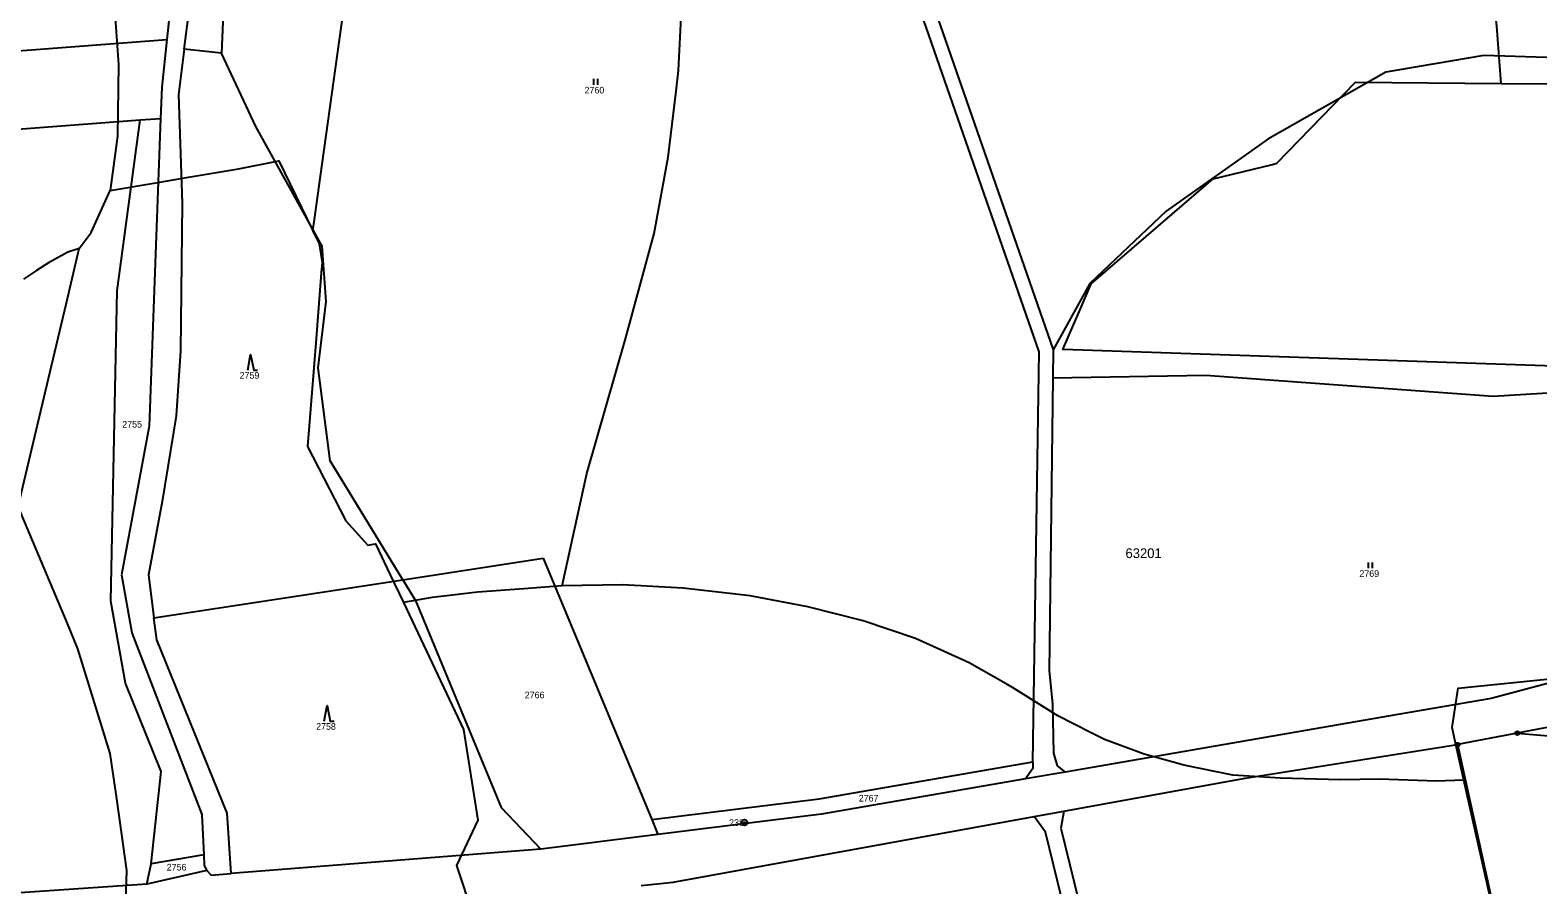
# Model space of a CAD drawing. Extents: x -546762 to -540209, y -1046851 to -1035694.
# Drawn here: x -540838.1 to -540451.5, y -1039687.3 to -1039468.3 of the extents above; entities that cross this region are included whole.
import ezdxf

# ---------------------------------------------------------------- set-up
doc = ezdxf.new("R2010")
doc.units = 0
for name, color, linetype in [('Vrstva 1', 7, 'Continuous'), ('Vrstva 17', 7, 'Continuous'), ('Vrstva 18', 7, 'Continuous'), ('Vrstva 24', 7, 'Continuous'), ('Vrstva 25', 7, 'Continuous'), ('Vrstva 52', 7, 'Continuous'), ('Vrstva 53', 7, 'Continuous')]:
    doc.layers.add(name, color=color, linetype=linetype)

msp = doc.modelspace()

# ---------------------------------------------------------------- linework, layer by layer
at = {"layer": 'Vrstva 1'}
msp.add_line((-540456.76, -1039648.44), (-540432.8, -1039650.55), dxfattribs=at)
for points in [[(-540579.38, -1039550.73), (-540626.46, -1039415.41)], [(-540622.88, -1039414.93), (-540575.81, -1039550.19)], [(-540799.07, -1039433.72), (-540803.05, -1039470.73)], [(-540798.57, -1039473.16), (-540795.73, -1039450.85)], [(-540787.96, -1039450.05), (-540789, -1039474.2)], [(-540966.72, -1039483.15), (-540803.05, -1039470.73)], [(-540803.05, -1039470.73), (-540804.36, -1039482.91)], [(-540798.57, -1039473.16), (-540800.05, -1039484.79)], [(-540789, -1039474.2), (-540798.57, -1039473.16)], [(-540780.25, -1039493.01), (-540789, -1039474.2)], [(-540465.38, -1039474.8), (-540490.49, -1039479.1)], [(-540414.42, -1039476.4), (-540465.38, -1039474.8)], [(-540490.49, -1039479.1), (-540520.75, -1039496.26)], [(-540804.36, -1039482.91), (-540804.66, -1039490.91)], [(-540800.05, -1039484.79), (-540799.11, -1039512.61)], [(-540963.66, -1039502.97), (-540809.89, -1039491.31)], [(-540815.81, -1039535.11), (-540809.89, -1039491.31)], [(-540809.89, -1039491.31), (-540804.66, -1039490.91)], [(-540804.66, -1039490.91), (-540807.61, -1039569.76)], [(-540763.22, -1039523.67), (-540780.25, -1039493.01)], [(-540520.75, -1039496.26), (-540546.78, -1039514.67)], [(-540799.11, -1039512.61), (-540799.5, -1039550.5)], [(-540546.78, -1039514.67), (-540566.37, -1039533.18)], [(-540762.16, -1039537.82), (-540763.22, -1039523.67)], [(-540566.37, -1039533.18), (-540575.81, -1039550.19)], [(-540817.37, -1039614.58), (-540815.81, -1039535.11)], [(-540764.23, -1039554.84), (-540762.16, -1039537.82)], [(-540799.5, -1039550.5), (-540800.68, -1039567.12)], [(-540580.98, -1039655.8), (-540579.38, -1039550.73)], [(-540575.81, -1039550.19), (-540575.89, -1039557.42)], [(-540761.13, -1039578.68), (-540764.23, -1039554.84)], [(-540575.89, -1039557.42), (-540576.8, -1039632.44)], [(-540575.89, -1039557.42), (-540536.65, -1039556.7)], [(-540536.65, -1039556.7), (-540462.98, -1039562.13)], [(-540462.98, -1039562.13), (-540442.01, -1039560.77)], [(-540800.68, -1039567.12), (-540804.21, -1039589.05)], [(-540807.61, -1039569.76), (-540814.7, -1039607.89)], [(-540742.54, -1039609.11), (-540761.13, -1039578.68)], [(-540804.21, -1039589.05), (-540807.77, -1039607.88)], [(-540742.54, -1039609.11), (-540706.51, -1039603.62)], [(-540706.51, -1039603.62), (-540678.7, -1039670.58)], [(-540814.7, -1039607.89), (-540811.98, -1039622.71)], [(-540807.77, -1039607.88), (-540806.37, -1039618.86)], [(-540806.37, -1039618.86), (-540742.54, -1039609.11)], [(-540742.54, -1039609.11), (-540739.29, -1039614.44)], [(-540813.6, -1039635.67), (-540817.37, -1039614.58)], [(-540739.29, -1039614.44), (-540717.27, -1039667.45)], [(-540805.64, -1039624.55), (-540806.37, -1039618.86)], [(-540811.98, -1039622.71), (-540794.04, -1039669.3)], [(-540787.57, -1039668.92), (-540805.64, -1039624.55)], [(-540576.8, -1039632.44), (-540575.9, -1039640.89)], [(-540439.7, -1039633.2), (-540463.46, -1039639.54)], [(-540804.48, -1039658.3), (-540813.6, -1039635.67)], [(-540575.9, -1039640.89), (-540575.69, -1039653.53)], [(-540463.46, -1039639.54), (-540487.42, -1039643.67)], [(-540487.42, -1039643.67), (-540572.72, -1039658.42)], [(-540431.58, -1039643.66), (-540456.76, -1039648.44)], [(-540456.76, -1039648.44), (-540472.09, -1039651.38)], [(-540575.69, -1039653.53), (-540574.75, -1039656.79)], [(-540526.56, -1039660.01), (-540472.09, -1039651.38)], [(-540472.09, -1039651.38), (-540452.38, -1039740.97)], [(-540807.09, -1039681.9), (-540804.48, -1039658.3)], [(-540635.78, -1039665.26), (-540580.98, -1039655.8)], [(-540581.01, -1039657.47), (-540582.83, -1039660.17)], [(-540580.98, -1039655.8), (-540581.01, -1039657.47)], [(-540574.75, -1039656.79), (-540572.72, -1039658.42)], [(-540582.83, -1039660.17), (-540635.19, -1039669.22)], [(-540572.72, -1039658.42), (-540582.83, -1039660.17)], [(-540573.01, -1039668.44), (-540526.56, -1039660.01)], [(-540678.7, -1039670.58), (-540635.78, -1039665.26)], [(-540794.04, -1039669.3), (-540793.57, -1039679.58)], [(-540786.53, -1039684.37), (-540787.57, -1039668.92)], [(-540717.27, -1039667.45), (-540707.18, -1039678.13)], [(-540673.19, -1039686.62), (-540580.65, -1039669.82)], [(-540635.19, -1039669.22), (-540648.31, -1039670.85)], [(-540580.65, -1039669.82), (-540573.01, -1039668.44)], [(-540577.71, -1039673.82), (-540580.65, -1039669.82)], [(-540573.01, -1039668.44), (-540573.82, -1039672.77)], [(-540678.7, -1039670.58), (-540677.11, -1039674.41)], [(-540648.31, -1039670.85), (-540677.11, -1039674.41)], [(-540573.82, -1039672.77), (-540553.17, -1039756.65)], [(-540677.11, -1039674.41), (-540707.18, -1039678.13)], [(-540557.3, -1039757.2), (-540577.71, -1039673.82)], [(-540793.57, -1039679.58), (-540807.09, -1039681.9)], [(-540793.57, -1039679.58), (-540793.44, -1039682.35)], [(-540707.18, -1039678.13), (-540786.53, -1039684.37)], [(-540808.19, -1039687.11), (-540807.09, -1039681.9)], [(-540792.74, -1039683.59), (-540808.19, -1039687.11)], [(-540793.44, -1039682.35), (-540792.74, -1039683.59)], [(-540792.74, -1039683.59), (-540791.65, -1039684.82)], [(-540791.65, -1039684.82), (-540786.53, -1039684.37)], [(-540808.19, -1039687.11), (-541007.11, -1039700.75)], [(-540681.43, -1039687.49), (-540673.19, -1039686.62)]]:
    msp.add_lwpolyline(points, dxfattribs=at)
at = {"layer": 'Vrstva 24'}
for centre, radius in [((-540456.76, -1039648.44), 0.5), ((-540456.76, -1039648.44), 0.1), ((-540472.09, -1039651.38), 0.5), ((-540472.09, -1039651.38), 0.1), ((-540654.94, -1039671.35), 0.75), ((-540654.94, -1039671.35), 0.1)]:
    msp.add_circle(centre, radius, dxfattribs=at)
at = {"layer": 'Vrstva 25'}
for p, q in [((-540693.52, -1039482.32), (-540693.52, -1039480.82)), ((-540692.52, -1039482.32), (-540692.52, -1039480.82)), ((-540494.9, -1039606.2), (-540494.9, -1039604.7)), ((-540493.9, -1039606.2), (-540493.9, -1039604.7))]:
    msp.add_line(p, q, dxfattribs=at)
for points in [[(-540782.26, -1039555.4), (-540781.56, -1039551.4), (-540780.76, -1039555.4), (-540779.76, -1039555.4)], [(-540762.66, -1039645.36), (-540761.96, -1039641.36), (-540761.16, -1039645.36), (-540760.16, -1039645.36)]]:
    msp.add_lwpolyline(points, dxfattribs=at)
at = {"layer": 'Vrstva 52'}
for points in [[(-540765.6, -1039519.76), (-540765.19, -1039516.82), (-540762.78, -1039499.56), (-540762.18, -1039495.29), (-540757.82, -1039464.07), (-540755.99, -1039423.53), (-540754.94, -1039399.2), (-540754.94, -1039393.07), (-540754.94, -1039380.64), (-540757.03, -1039361.02), (-540758.37, -1039350.85), (-540758.97, -1039338.44), (-540758.22, -1039328.88), (-540756.88, -1039322), (-540756.26, -1039320.06), (-540754.49, -1039314.53), (-540747.09, -1039301.83), (-540735.59, -1039287.18), (-540734.98, -1039286.5), (-540730.2, -1039281.21), (-540728.36, -1039279.17), (-540725.92, -1039276.46), (-540718.34, -1039267.04)], [(-540833.47, -1039354.59), (-540833.93, -1039358.54), (-540833.73, -1039363.08), (-540833.52, -1039367.7), (-540833.41, -1039370.05), (-540833.15, -1039378.68), (-540830.79, -1039393.33), (-540829.59, -1039400.7), (-540828.88, -1039405.02), (-540828.77, -1039405.72), (-540827.58, -1039411.35), (-540826.56, -1039416.22), (-540824.59, -1039425.59), (-540818.84, -1039447.83), (-540816.48, -1039462.73), (-540815.44, -1039477.12), (-540815.7, -1039495.43), (-540817.55, -1039509.42)], [(-540460.88, -1039481.97), (-540461.97, -1039467.28), (-540463.91, -1039450.24), (-540466.15, -1039436.94), (-540468.39, -1039426.93), (-540471.23, -1039416.31), (-540473.77, -1039408.54), (-540477.76, -1039399.55)], [(-540695.37, -1039581.89), (-540685.44, -1039547.37), (-540678.12, -1039520.43), (-540674.46, -1039500.81), (-540672.47, -1039483.95), (-540671.84, -1039478.64), (-540671.09, -1039463.25)], [(-540470.45, -1039660.46), (-540472.66, -1039650.59), (-540473.47, -1039646.99), (-540471.91, -1039636.93), (-540437.47, -1039633.39), (-540434.3, -1039632.76), (-540432.22, -1039631.36), (-540418.21, -1039611.69), (-540416.61, -1039609.45), (-540402.98, -1039550.99), (-540447.1, -1039554.39), (-540573.26, -1039550.12), (-540568.62, -1039539.31), (-540566.03, -1039533.29), (-540534.77, -1039506.37), (-540519.57, -1039502.69), (-540518.38, -1039502.4), (-540498.22, -1039481.67), (-540460.88, -1039481.97)], [(-540460.88, -1039481.97), (-540434.19, -1039482.18)], [(-540817.55, -1039509.42), (-540805.38, -1039507.35), (-540797.47, -1039506.01), (-540784.63, -1039503.83), (-540774.3, -1039501.81), (-540765.6, -1039519.76)], [(-540825.54, -1039524.26), (-540822.4, -1039520.14), (-540817.55, -1039509.42)], [(-540765.6, -1039519.76), (-540764, -1039523.05), (-540763.22, -1039527.86), (-540763.43, -1039530.46), (-540764.85, -1039548.45), (-540766.95, -1039575.02), (-540757.11, -1039594.07), (-540751.52, -1039600.27), (-540749.51, -1039599.96), (-540745.77, -1039607.86), (-540742.39, -1039614.99)], [(-540870.6, -1039803.26), (-540814.16, -1039802.15), (-540743.32, -1039794.87), (-540741.77, -1039782), (-540813.73, -1039697.08), (-540813.64, -1039694.29), (-540813.28, -1039683.59), (-540815.19, -1039670.17), (-540816.05, -1039664.11), (-540817.54, -1039653.63), (-540825.83, -1039626.85), (-540828.55, -1039620.38), (-540841.16, -1039590.4), (-540832.2, -1039552.54), (-540828.8, -1039538.17), (-540825.54, -1039524.26)], [(-540825.54, -1039524.26), (-540828.45, -1039525.22), (-540831.64, -1039526.96), (-540833.38, -1039527.91), (-540836.49, -1039529.93), (-540839.8, -1039532.09)], [(-540701.64, -1039610.66), (-540695.37, -1039581.89)], [(-540701.64, -1039610.66), (-540711.46, -1039611.42), (-540723.39, -1039612.35), (-540729.78, -1039613.09), (-540735.04, -1039613.69), (-540742.39, -1039614.99)], [(-540517.48, -1039659.95), (-540529.73, -1039659.2), (-540542.28, -1039656.66), (-540543.5, -1039656.32), (-540552.43, -1039653.82), (-540562.59, -1039650.09), (-540566.03, -1039648.32), (-540574.54, -1039643.96), (-540586.23, -1039636.71), (-540587.84, -1039635.8), (-540597.32, -1039630.43), (-540611.06, -1039624.16), (-540624.5, -1039619.67), (-540638.69, -1039616.09), (-540653.48, -1039613.25), (-540670.66, -1039611.3), (-540686.19, -1039610.41), (-540701.64, -1039610.66)], [(-540742.39, -1039614.99), (-540726.99, -1039647.49), (-540723.3, -1039670.73), (-540728.78, -1039682.36), (-540720.24, -1039708.12)], [(-540550.13, -1039749.75), (-540538.93, -1039748.47), (-540458.81, -1039741.53), (-540452.38, -1039740.97), (-540470.45, -1039660.46)], [(-540470.45, -1039660.46), (-540477.45, -1039660.7), (-540492.09, -1039660.25), (-540502.1, -1039660.4), (-540517.48, -1039659.95)]]:
    msp.add_lwpolyline(points, dxfattribs=at)

# ---------------------------------------------------------------- texts
at = {"layer": 'Vrstva 17'}
msp.add_text('238', height=1.7, dxfattribs=at).set_placement((-540658.86, -1039672.2))
at = {"layer": 'Vrstva 18'}
for s, p in [('2760', (-540695.93, -1039484.53)), ('2759', (-540784.37, -1039557.61)), ('2755', (-540814.47, -1039570.15)), ('2769', (-540497.25, -1039608.41)), ('2766', (-540711.26, -1039639.5)), ('2758', (-540764.76, -1039647.57)), ('2767', (-540625.62, -1039665.95)), ('2756', (-540803.07, -1039683.63))]:
    msp.add_text(s, height=1.7, dxfattribs=at).set_placement(p)
at = {"layer": 'Vrstva 53'}
msp.add_text('63201', height=2.5, dxfattribs=at).set_placement((-540557.23, -1039603.58))

doc.saveas('drawing.dxf')
